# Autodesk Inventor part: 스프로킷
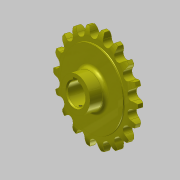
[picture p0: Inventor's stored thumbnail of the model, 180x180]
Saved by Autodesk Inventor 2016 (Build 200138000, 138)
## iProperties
Created: 2016-03
Part Number: 스프로킷
Material: 강철, 탄소
Document SubType Name: Modeling
Designer: mduedu
Density: 7.87 g/cm^3
Mass: 300.023 g
Surface Area: 127.848 cm^2
Volume: 38.1224 cm^3
Appearance: 노란색
Author: mduedu
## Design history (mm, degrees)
sketch "스케치1"
  geometry: L1 (0, 5)-(29.5, 5); L2 (29.5, 5)-(29.5, 4.1); L3 (30, 3.6)-(33.625, 3.6); L4 (40, 2)-(40, 0); L5 (40, 0)-(0, 0); L6 (0, 0)-(0, 5); L7 (0, -5)-(29.5, -5); L8 (29.5, -5)-(29.5, -4.1); L9 (30, -3.6)-(33.625, -3.6); L10 (40, -2)-(40, 0); L11 (0, 0)-(0, -5); A1 r 13.5 centre (33.625, -9.9) between (40, 2) and (33.625, 3.6); A2 r 13.5 centre (33.625, 9.9) between (33.625, -3.6) and (40, -2); A3 r 0.5 centre (30, 4.1) between (29.5, 4.1) and (30, 3.6); A4 r 0.5 centre (30, -4.1) between (30, -3.6) and (29.5, -4.1); 2 further points
  constraints: 22 end point, 8 point on circle, 6 symmetric about line, 5 tangent, 4 centre point, 4 parallel, 4 point on line, 1 equal radius, 1 horizontal, 1 perpendicular, 1 other
  dimensions: "d0" = 80 diameter of L4 L6; "d2" = 59 diameter of L2 L6; "d3" = 1.6 vertical distance of L4.start L3.end; "d4" = 3.6 distance from line of L4.end L3; "d5" = 5 distance between parallel lines of L5 L1; "d6" = 13.5 radius of A1; "d15" = 0.5 radius of A3
revolve "회전1" sketch "스케치1" stored, may be unused: angle "d7" = 90 deg
sketch "스케치2" dims "d8" = 65.2, "d11" = 80
  geometry: L1 (0, 0)-(0, 32.6); A1 r 36.57 centre (0, 0) between (-16.231, 32.771) and (0, 36.57); A2 r 3.97 centre (0, 36.57) between (-3.866, 35.665) and (0, 32.6); A3 r 12.7 centre (-16.231, 32.771) between (-3.866, 35.665) and (-5.534, 39.615); A4 r 12.7 centre (16.231, 32.771) between (5.534, 39.615) and (3.866, 35.665); A5 r 3.97 centre (0, 36.57) between (0, 32.6) and (3.866, 35.665); A6 r 40 centre (0, 0) between (5.534, 39.615) and (-5.534, 39.615); 2 further points
  constraints: 12 point on circle, 6 centre point, 4 coincident, 3 symmetric about line, 2 end point, 1 point on line, 1 tangent, 1 vertical, 1 vertical alignment, 7 other
  dimensions: "d10" = 73.14 diameter of A1; "d12" = 12.7 radius of A3
extrude "돌출1" cut sketch "스케치2" stored distance "d13" = 10; taper "d14" = 0 deg
sketch "스케치3"
  geometry: C1 r 13.5 at (0, 0); 1 further point
  constraints: 1 centre point, 1 coincident
  dimensions: "d19" = 27 diameter of C1
extrude "돌출2" join sketch "스케치3" distance "d20" = 13; taper "d21" = 0 deg
fillet "모깎기1" dims "d22" = 3
sketch "스케치4"
  geometry: L1 (-2.5, 0)-(2.5, 0); L2 (2.5, 0)-(2.5, 10.8); L3 (2.5, 10.8)-(-2.5, 10.8); L4 (-2.5, 10.8)-(-2.5, 0); C1 r 8.5 at (0, 0); 2 further points
  constraints: 8 end point, 2 coincident, 2 parallel, 1 centre point, 1 horizontal, 1 midpoint, 1 perpendicular
  dimensions: "d23" = 17 diameter of C1; "d25" = 5 distance of L2.end L3.end; "d26" = 10.8 distance of L1.end L2.end
extrude "돌출3" cut sketch "스케치4" stored distance "d27" = 8; taper "d28" = 0 deg
chamfer "모따기1" distance "d29" = 1; stored, may be unused: second distance "d30" = 2, angle "d31" = 45 deg
node "작업 평면1"
sketch "스케치5"
  geometry: L1 (13.5, 13)-(-13.5, 13) reference; 2 further points
  constraints: 1 vertical alignment
  dimensions: "d32" = 4 distance from line of point (0, 9) L1
hole "구멍1" sketch "스케치5" at (0, 9) diameter "d33" = 2.459; stored, may be unused: countersink angle "d37" = 90 deg, drill point angle "d39" = 118 deg; dims "d34" = 6, "d35" = 4, "d36" = 2, "d38" = 8
node "솔리드1"
pattern_circular "원형 패턴1" dims angle "d17" = 360 deg
